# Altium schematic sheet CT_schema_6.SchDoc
size 278 x 170 mm
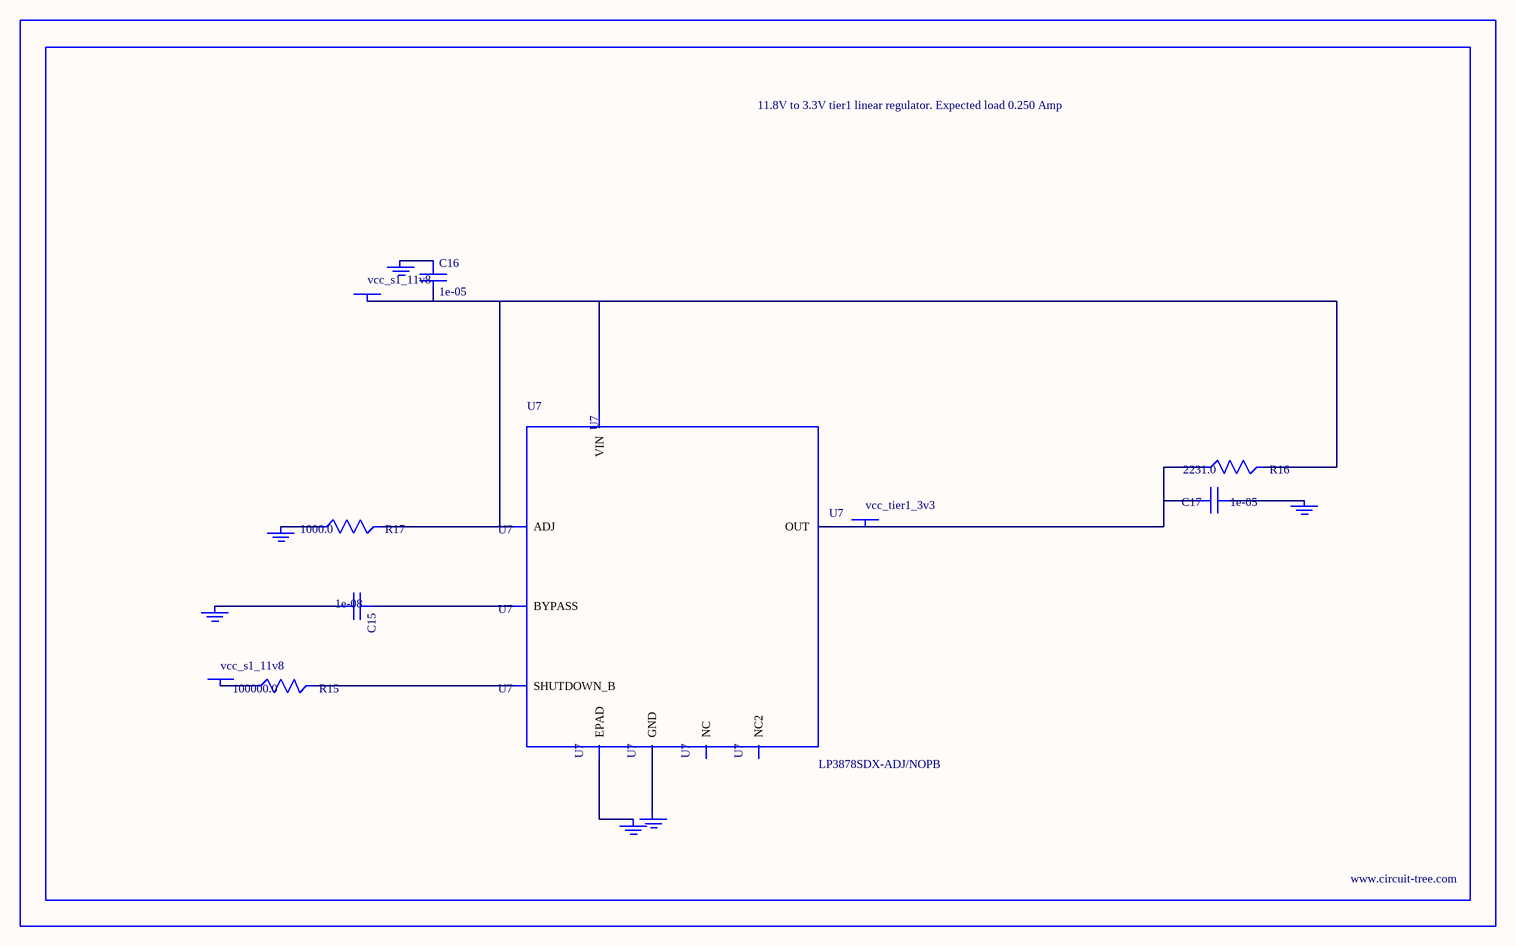
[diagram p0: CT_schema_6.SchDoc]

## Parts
BORDER5  (no value)
C15  1e-08  [C0402]
C16  1e-05  [C1210]
C17  1e-05  [C1210]
GND_INSTANCE_5_0  (no value)
GND_INSTANCE_5_1  (no value)
GND_INSTANCE_5_2  (no value)
GND_INSTANCE_5_3  (no value)
GND_INSTANCE_5_4  (no value)
GND_INSTANCE_5_5  (no value)
POWER_INSTANCE_5_0  vcc_s1_11v8
POWER_INSTANCE_5_1  vcc_s1_11v8
POWER_INSTANCE_5_2  vcc_tier1_3v3
R15  100000.0  [R0603]
R16  2231.0  [R0603]
R17  1000.0  [R0603]
U7  LP3878SDX-ADJ/NOPB  [WSON-8]

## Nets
NetC15_1: C15.1 U7.1(BYPASS)
NetC15_2: C15.2 GND_INSTANCE_5_0.0(GND)
NetC16_1: C16.1 GND_INSTANCE_5_1.0(GND)
NetC16_2: C16.2 POWER_INSTANCE_5_0.0(PWR) R16.2 R17.2 U7.4(VIN) U7.6(ADJ)
NetC17_1: C17.1 GND_INSTANCE_5_2.0(GND)
NetC17_2: C17.2 POWER_INSTANCE_5_2.0(PWR) R16.1 U7.5(OUT)
NetGND_INSTANCE_5_3_0: GND_INSTANCE_5_3.0(GND) R17.1
NetGND_INSTANCE_5_4_0: GND_INSTANCE_5_4.0(GND) U7.PAD(EPAD)
NetGND_INSTANCE_5_5_0: GND_INSTANCE_5_5.0(GND) U7.3(GND)
NetPOWER_INSTANCE_5_1_0: POWER_INSTANCE_5_1.0(PWR) R15.1
NetR15_2: R15.2 U7.8(SHUTDOWN_B)

Not connected (* = marked no-connect by the designer): U7 2(NC) 7(NC2)

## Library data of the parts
BORDER5 = BORDER_PAGE5
C15 = C0402C103K3RAC
C16 = C1210C106K5PACTU
C17 = GRM32DR61E106MA12L
GND_INSTANCE_5_0-GND_INSTANCE_5_5 = GND
POWER_INSTANCE_5_0-POWER_INSTANCE_5_2 = PWR
R15 = RC0603JR-07100KL
R16 = R16
R17 = RC0603JR-071KL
